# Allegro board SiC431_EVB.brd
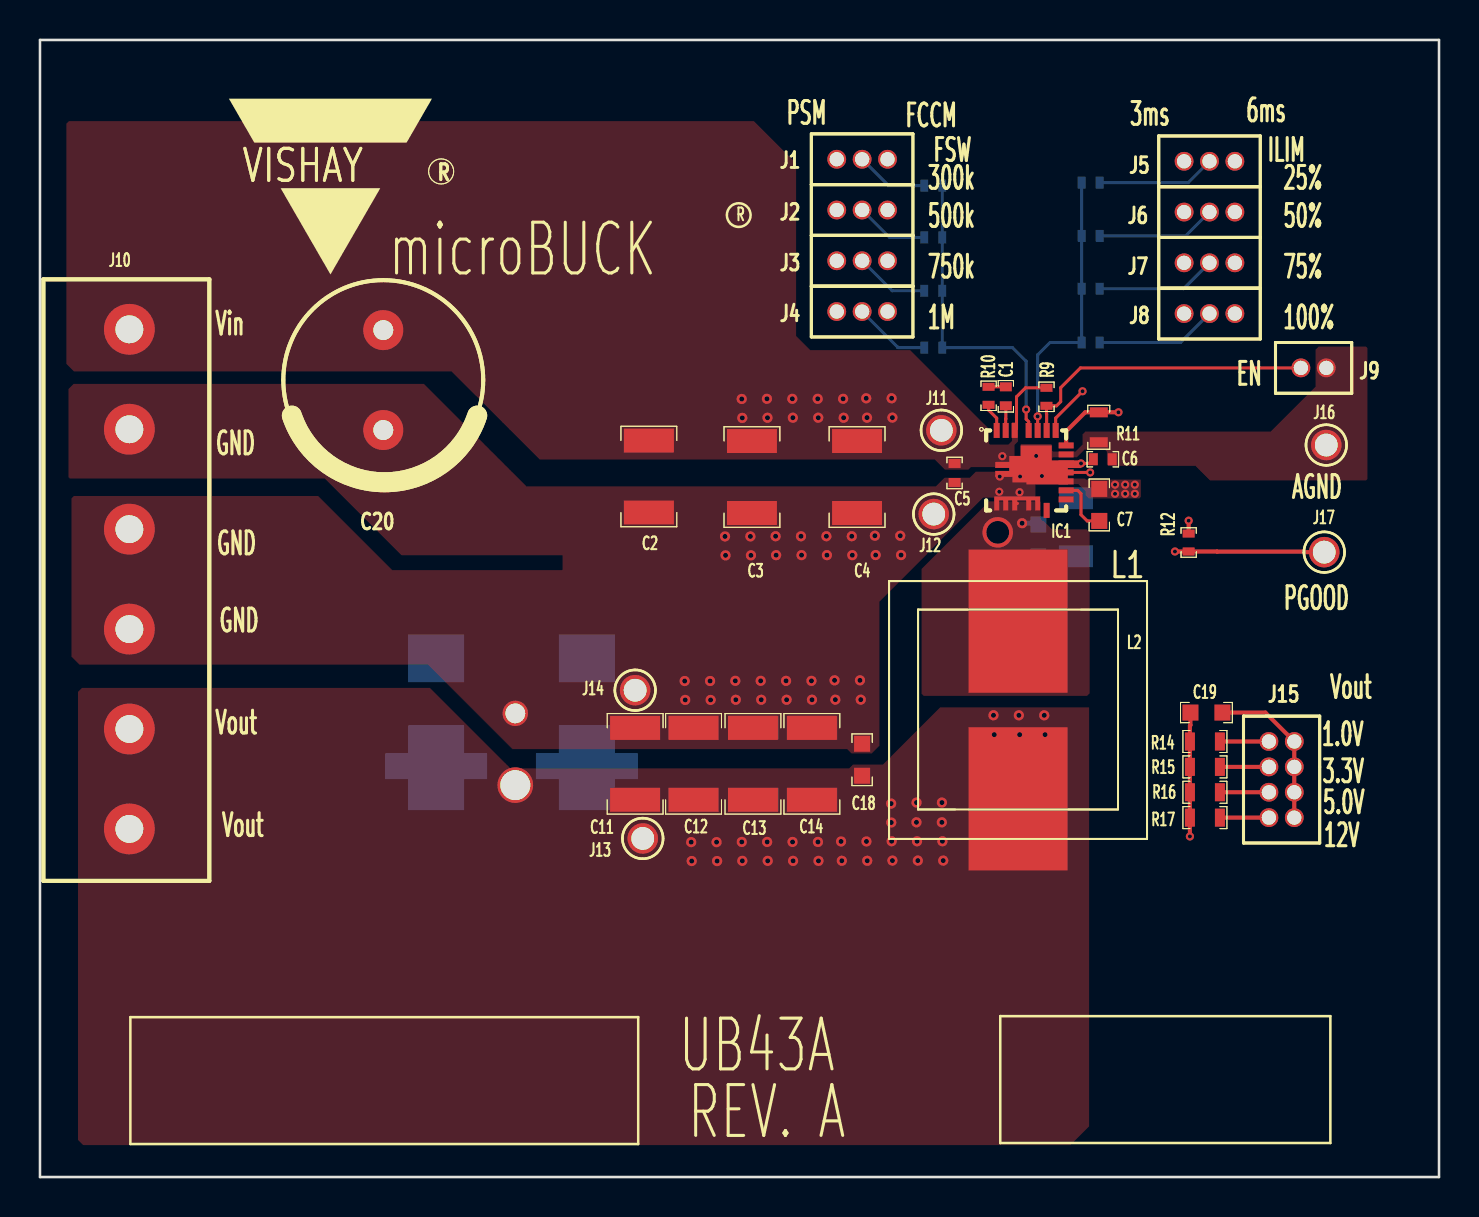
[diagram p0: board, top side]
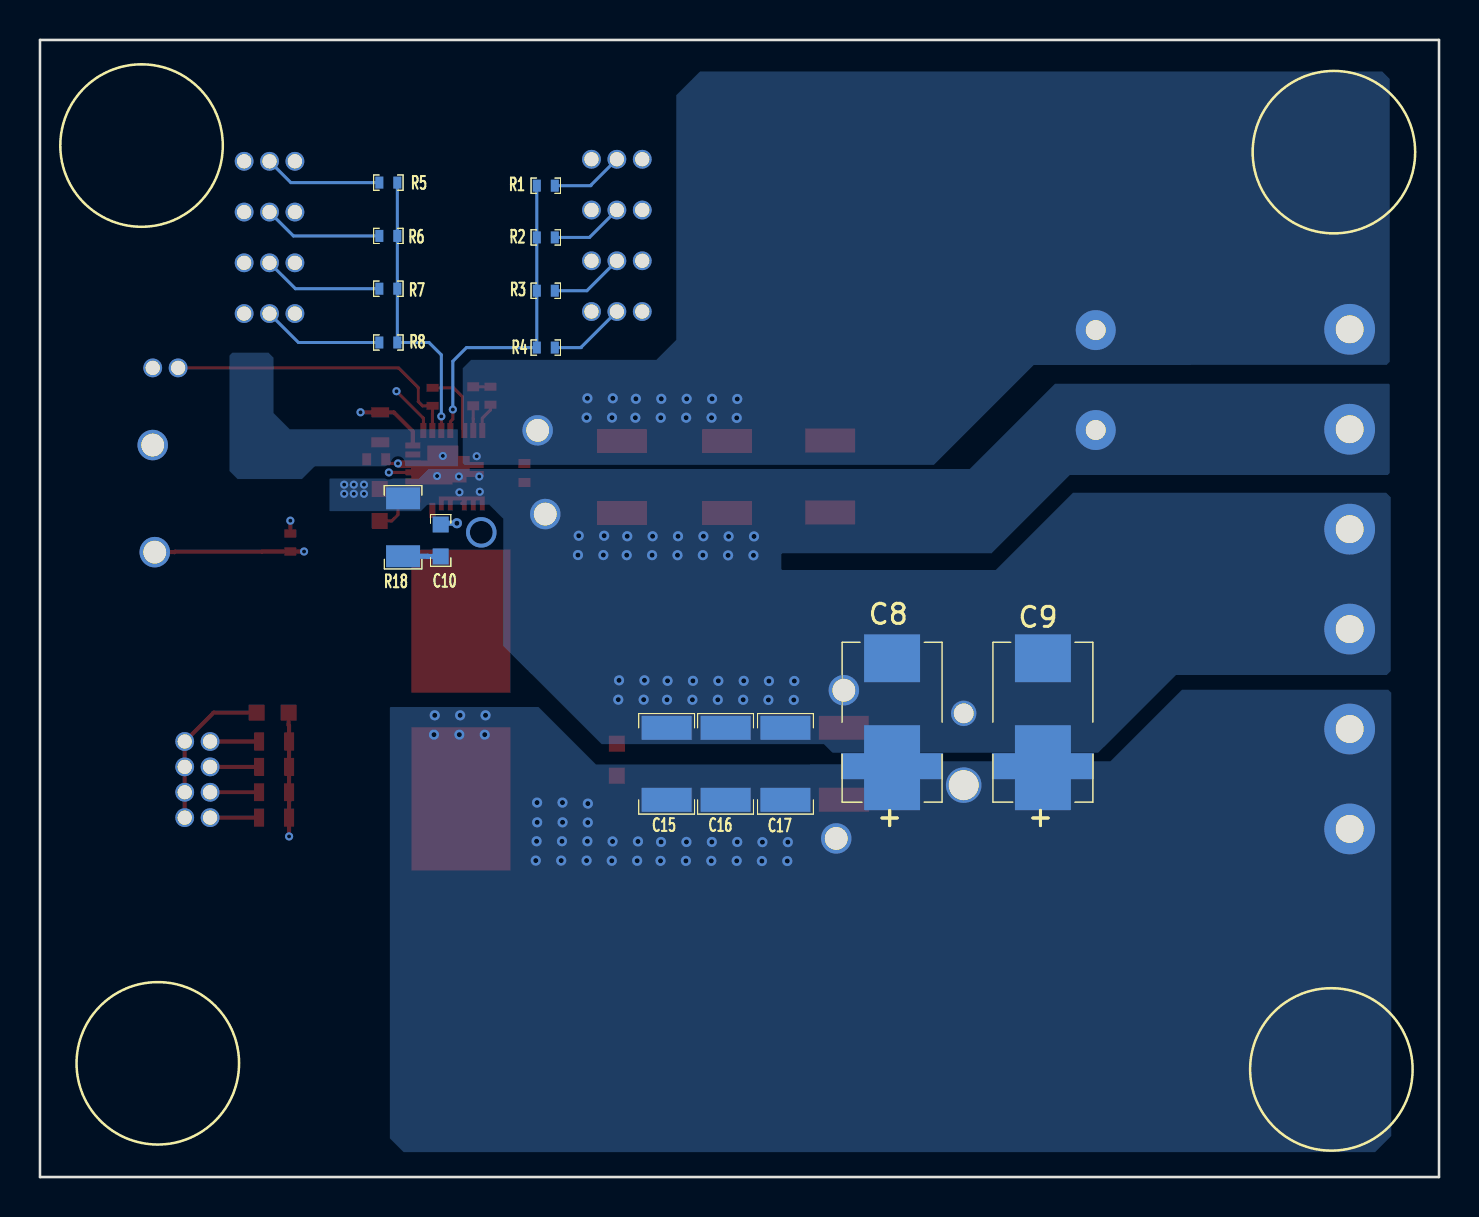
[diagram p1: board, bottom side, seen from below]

Outline 69.98 x 56.9 mm; copper layers: TOP, LAYER2, LAYER3, LAYER4, LAYER5, BOTTOM. Coordinates in mm from the lower left corner of the outline.
Outline path: 0,56.9 0,0 69.98,0 69.98,56.9 0,56.9

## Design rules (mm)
constraint set DEFAULT: min track width 0.152

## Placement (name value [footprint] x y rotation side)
C1  100n  [C0402-TDK1]  48.31 39.07 270 top
C2  22uF  [C1210-TDK]  30.45 35.05 270 top
C3  22uF  [C1210-TDK]  35.61 35.03 270 top
C4  22uF  [C1210-TDK]  40.87 35.03 270 top
C5  0.1uF  [C0402-TDK]  45.75 35.23 270 top
C6  0.1u  [C0402-TDK1]  53.16 35.92 0 top
C7  1u  [C0603-TDK1]  52.98 33.63 90 top
C8  DNP  [POSCAP]  27.36 22.76 90 bottom
C9  DNP  [POSCAP]  19.81 22.76 90 bottom
C10  DNP  [C0603-TDK1]  49.94 31.85 270 bottom
C11  22uF  [C1210-TDK]  29.77 20.68 90 top
C12  22uF  [C1210-TDK]  32.69 20.68 90 top
C13  22uF  [C1210-TDK]  35.66 20.68 90 top
C14  22uF  [C1210-TDK]  38.61 20.68 90 top
C15  22uF  [C1210-TDK]  38.63 20.68 90 bottom
C16  22uF  [C1210-TDK]  35.69 20.68 90 bottom
C17  22uF  [C1210-TDK]  32.69 20.68 90 bottom
C18  0.1u  [C0603-TDK1]  41.12 20.88 90 top
C19  22n  [C0603-TDK1]  58.34 23.24 180 top
C20  220uF  [CAP10P2X5]  17.17 39.88 270 top
IC1  SiC431  [SIC431M]  49.33 35.36 0 top
J1  CON3  [MINIJUMPER3]  42.39 50.93 180 top
J2  CON3  [MINIJUMPER3]  42.39 48.39 180 top
J3  CON3  [MINIJUMPER3]  42.39 45.85 180 top
J4  CON3  [MINIJUMPER3]  42.39 43.31 180 top
J5  CON3  [MINIJUMPER3]  59.77 50.83 180 top
J6  CON3  [MINIJUMPER3]  59.77 48.29 180 top
J7  CON3  [MINIJUMPER3]  59.77 45.75 180 top
J8  CON3  [MINIJUMPER3]  59.77 43.21 180 top
J9  CON2  [MINIJUMPER2]  64.34 40.49 180 top
J10  -  [CON6]  4.47 42.42 270 top
J11  VIN+s  [TP30]  45.09 37.36 0 top
J12  VIN-S  [TP30]  44.7 33.17 0 top
J13  VO+S  [TP30]  30.15 16.94 0 top
J14  VO-S  [TP30]  29.77 24.36 0 top
J15  CON8A  [MINIJUMPER2X4]  61.47 21.79 0 top
J16  AGND  [TP30]  64.34 36.63 0 top
J17  PGOOD  [TP30]  64.24 31.27 0 top
L1  0.22uH  [IHLP]  48.92 23.37 90 top
L2  0.22uH  [HCUVDE1]  48.92 23.39 90 top
NOREF  -  []  14.53 45.16 0 top
PB  CON2  [2PROBE]  23.77 19.61 135 top
R1  51k  [R0402-VISHAY1]  44.68 49.61 180 bottom
R2  100k  [R0402-VISHAY1]  44.68 47.02 180 bottom
R3  200k  [R0402-VISHAY1]  44.68 44.35 180 bottom
R4  510k  [R0402-VISHAY1]  44.68 41.5 180 bottom
R5  51k  [R0402-VISHAY1]  52.55 49.76 0 bottom
R6  100k  [R0402-VISHAY1]  52.55 47.09 0 bottom
R7  200k  [R0402-VISHAY1]  52.55 44.45 0 bottom
R8  510k  [R0402-VISHAY1]  52.55 41.76 0 bottom
R9  100k  [R0402-VISHAY1]  50.34 39.04 90 top
R10  0  [R0402-VISHAY1]  47.45 39.09 270 top
R11  10k  [R0603-VISHAY]  52.96 37.52 90 top
R12  100k  [R0402-VISHAY1]  57.45 31.75 90 top
R14  10k  [R0603-VISHAY]  58.27 21.79 0 top
R15  10k  [R0603-VISHAY]  58.27 20.52 0 top
R16  10k  [R0603-VISHAY]  58.27 19.25 0 top
R17  10k  [R0603-VISHAY]  58.27 17.98 0 top
R18  DNP  [R1206-VISHAY]  51.82 32.51 270 bottom

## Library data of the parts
C1-C6 C11-C19 = CAPACITOR NON-POL
C7 C10 = CAP NP
C8 C9 = POSCAP
C20 = CAP
IC1 = SiC431_2
J1-J8 = CON3: User Part Number: ***
J9 = CON2: User Part Number: ***
J10 = CON6
J11-J14 J16 J17 = CON1
J15 = CON8A
L1 L2 = INDUCTOR
PB = CON2
R1-R8 R10 R12 R14-R17 = R
R9 R11 R18 = RESISTOR

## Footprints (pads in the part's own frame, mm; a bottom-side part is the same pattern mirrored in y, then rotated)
2PROBE
  round 1.778 hole 1.499: 1(0,0)
  round 1.27 hole 0.991: 2(2.54,-2.54)
C0402-TDK
  rect 0.45x0.6 smd: 1(-0.475,0) 2(0.475,0)
C0402-TDK1
  rect 0.45x0.6 smd: 1(-0.475,0) 2(0.475,0)
C0603-TDK1
  rect 0.8x0.8 smd: 1(-0.8,0) 2(0.8,0)
C1210-TDK
  rect 1.2x2.5 smd: 1(-1.8,0) 2(1.8,0)
CAP10P2X5
  round 2 hole 1: 1(-2.5,0) 2(2.5,0)
CON6
  round 2.54 hole 1.397: 1(0,0) 2(5,0) 3(10,0) 4(15,0) 5(20,0) 6(25,0)
HCUVDE1
  custom 0.9x0.9 smd: 1(-3.65,0) 2(3.65,0)
IHLP
  rect 7.163x4.953 smd: 1(-4.445,0) 2(4.445,0)
MINIJUMPER2
  round 0.94 hole 0.711: 1(0,0) 2(1.27,0)
MINIJUMPER2X4
  round 0.94 hole 0.711: 1(0,0) 2(1.27,0) 3(0,-1.27) 4(1.27,-1.27) 5(0,-2.54) 6(1.27,-2.54) 7(0,-3.81) 8(1.27,-3.81)
MINIJUMPER3
  round 0.94 hole 0.711: 1(0,0) 2(1.27,0) 3(2.54,0)
POSCAP
  rect 2.4x2.8 smd: 1(-3.2,0) 2(3.2,0)
  custom 0.675x0.675 smd: 3(-1.5,0)
R0402-VISHAY1
  rect 0.4x0.6 smd: 1(-0.45,0) 2(0.45,0)
R0603-VISHAY
  rect 0.5x0.9 smd: 1(-0.75,0) 2(0.75,0)
R1206-VISHAY
  rect 1.1x1.7 smd: 1(-1.45,0) 2(1.45,0)
SIC431M
  custom 0.263x0.263 smd: 1(-0.65,0.2)
  round 0 smd: 2(-1.499,0.406) 4(-2.007,-0.914) 6(-0.889,-2.134) 7(-0.432,-2.184) 8(0.076,-2.184) 9(0.457,-2.159)
  custom 0.3x0.3 smd: 3(1.03,-0.1)
  custom 0.175x0.175 smd: 5(-0.45,-1.65)
  rect 0.3x0.75 smd: 10(1.025,-2) 18(1.475,2) 19(1.025,2) 20(0.575,2) 21(0.125,2) 22(-0.575,2) 23(-1.025,2) 24(-1.475,2)
  rect 0.75x0.3 smd: 11(2,-1.45) 12(2,-1) 13(2,-0.55) 14(2,-0.1) 15(2,0.35) 16(2,0.8) 17(2,1.25)
  rect 1.55x1.05 smd: 25(0.5,0.725)
TP30
  round 1.524 hole 1.143: 1(0,0)

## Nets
GND_POWER: C2.2 C3.2 C4.2 C5.2 C6.2 C7.2 C8.2 C8.3 C9.2 C9.3 C11.2 C12.2 C13.2 C14.2 C15.2 C16.2 C17.2 C18.2 C20.2 IC1.3 IC1.4 IC1.13 IC1.16 IC1.25 J1.3 J2.3 J3.3 J4.3 J5.3 J6.3 J7.3 J8.3 J9.1 J10.2 J10.3 J10.4 J12.1 J14.1 J16.1 PB.2 R11.1 R18.1
VDD1: C6.1 IC1.15 J1.1 J2.1 J3.1 J4.1 J5.1 J6.1 J7.1 J8.1 R12.2
VIN: C2.1 C3.1 C4.1 C5.1 C20.1 IC1.1 IC1.2 IC1.22 J10.1 J11.1 R9.2
BOOT: C1.2 IC1.23
MODE1: IC1.21 R1.1 R2.1 R3.1 R4.1
MODE2: IC1.20 R5.1 R6.1 R7.1 R8.1
PGD: IC1.14 J17.1 R12.1
PHASE: IC1.24 R10.2
VO: C8.1(P) C9.1(P) C11.1 C12.1 C13.1 C14.1 C15.1 C16.1 C17.1 C18.1 C19.2 IC1.18(VOUT) J10.5 J10.6 J13.1 L1.1 L2.1 PB.1 R14.1 R15.1 R16.1 R17.1
N10425435: C10.1 IC1.5 IC1.6 IC1.7 IC1.8 IC1.9 L1.2 L2.2
N10425735: IC1.19 J9.2 R9.1
N10425943: C1.1 R10.1
N10491860: C19.1 IC1.17 J15.2 J15.4 J15.6 J15.8 R11.2
N10497600: C7.1 IC1.12
N10592056: J1.2 R1.2
N10592279: J2.2 R2.2
N10592308: J3.2 R3.2
N10592330: J4.2 R4.2
N10602058: J5.2 R5.2
N10602062: J6.2 R6.2
N10602066: J7.2 R7.2
N10602070: J8.2 R8.2
N10625993: C10.2 R18.2
N10654889: J15.1 R14.2
N10668036: J15.3 R15.2
N10668228: J15.5 R16.2
N10668284: J15.7 R17.2

Pads without a net: IC1 10 11

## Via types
v1: diameter 0.508, hole 0.254, TOP to BOTTOM, 81 vias
v2: diameter 1.524, hole 1.143, TOP to BOTTOM, 1 via
v3: diameter 0.406, hole 0.203, TOP to BOTTOM, 22 vias

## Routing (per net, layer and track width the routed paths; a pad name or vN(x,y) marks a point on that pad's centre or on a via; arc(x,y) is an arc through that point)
GND_POWER:
  vias: v1(32.25,24.82) v1(32.27,23.87) v1(33.52,24.82) v1(33.54,23.87) v1(34.26,32.05) v1(34.29,31.11) v1(34.78,24.83) v1(34.8,23.88) v1(35.53,32.05) v1(35.56,31.11) v1(36.05,24.83) v1(36.07,23.88) v1(36.79,32.06) v1(36.82,31.12) v1(37.32,24.83) v1(37.34,23.88) v1(38.06,32.06) v1(38.09,31.12) v1(38.59,24.83) v1(38.61,23.88) v1(39.33,32.06) v1(39.36,31.12) v1(39.74,24.85) v1(39.78,23.89) v1(40.6,32.06) v1(40.63,31.12) v1(41.01,24.85) v1(41.05,23.89) v1(41.76,32.09) v1(41.8,31.12) v1(43.03,32.09) v1(43.07,31.12) v3(48.01,35.05) v3(47.98,34.29) v3(49.02,35.05) v3(49,34.26) v3(49.83,36.08) v3(50.11,35.08) v3(53.77,34.65) v3(53.77,34.19) v3(54.28,34.65) v3(54.28,34.19) v3(54.76,34.65) v3(54.76,34.19)
VDD1: length 51.1
  TOP w0.152: 52.48,35.71 52.48,35.71 C6.1 ; 52.48,35.71 52.68,35.91 52.68,35.92 ; 52.48,35.71 v3(52.07,35.71) IC1.15
  TOP w0.203: R12.2 v3(57.45,32.84)
  LAYER3 w0.152: 51.56,38.88 48.95,41.5 43.15,41.5 42.39,42.27 J4.1 J3.1 J2.1 J1.1 ; 51.56,38.88 51.56,40.01 52.6,41.05 59.03,41.05 59.77,41.78 J8.1 J7.1 J6.1 J5.1 ; 51.56,38.88 52.07,38.38 v3(52.07,35.71) 55.25,35.71 57.45,33.5 v3(57.45,32.84)
VIN: length 3.4
  TOP w0.152: R9.2 49.29,39.49 48.84,39.04 48.84,37.45 IC1.22
  vias: v1(35.1,38.93) v1(35.13,37.99) v1(36.36,38.94) v1(36.39,37.99) v1(37.63,38.94) v1(37.66,37.99) v1(38.9,38.94) v1(38.93,37.99) v1(40.17,38.94) v1(40.2,37.99) v1(41.33,38.97) v1(41.37,38) v1(42.6,38.97) v1(42.64,38) v3(48.13,36.07)
BOOT: length 1.2
  TOP w0.152: IC1.23 48.3,37.94 48.31,37.94 C1.2
MODE1: length 16.1
  TOP w0.152: IC1.21 49.45,37.8 49.33,37.92 v3(49.33,38.4)
  BOTTOM w0.152: R1.1 R2.1 R3.1 R4.1 48.64,41.5 49.33,40.82 v3(49.33,38.4)
MODE2: length 14.2
  TOP w0.152: IC1.20 v3(49.9,38.06)
  BOTTOM w0.152: v3(49.9,38.06) 49.9,41.14 50.52,41.76 R8.1 R7.1 R6.1 R5.1
PGD: length 16
  TOP w0.152: v3(52.53,35.26) IC1.14
  TOP w0.203: v3(56.77,31.3) R12.1 58.87,31.3 58.88,31.29 63.22,31.29 63.25,31.27 J17.1
  LAYER3 w0.152: v3(56.77,31.3) 56.77,33.68 55.19,35.26 v3(52.53,35.26)
PHASE: length 1.5
  TOP w0.152: IC1.24 47.85,37.97 47.45,38.38 R10.2
VO: length 63.2
  TOP w0.152: IC1.18 50.8,37.97 v3(52.15,39.32)
  TOP w0.203: v3(57.52,17.04) R17.1 R16.1 R15.1 R14.1 57.52,22.59 57.54,22.61 C19.2
  LAYER3 w0.152: J13.1 31.9,15.19 56.77,15.19 57.52,15.94 v3(57.52,17.04) 58.12,17.64 58.12,33.35 v3(52.15,39.32)
  vias: v1(32.57,16.76) v1(32.6,15.81) v1(33.84,16.76) v1(33.87,15.81) v1(35.1,16.77) v1(35.13,15.82) v1(36.37,16.77) v1(36.4,15.82) v1(37.64,16.77) v1(37.67,15.82) v1(38.91,16.77) v1(38.94,15.82) v1(40.07,16.79) v1(40.11,15.83) v1(41.34,16.79) v1(41.38,15.83) v1(42.57,18.69) v1(42.58,17.74) v1(42.6,16.8) v1(42.64,15.83) v1(43.84,18.74) v1(43.84,17.75) v1(43.87,16.8) v1(43.91,15.83) v1(45.11,18.74) v1(45.11,17.75) v1(45.14,16.8) v1(45.18,15.83) v1(47.69,23.1) v1(47.73,22.14) v1(48.96,23.1) v1(49,22.14) v1(50.23,23.1) v1(50.27,22.14)
N10425435: length 0.8
  BOTTOM w0.254: v1(49.12,32.72) 49.87,32.72 C10.1
  vias: v2(47.9,32.26)
N10425735: length 15.2
  TOP w0.152: J9.2 52.04,40.49 51.05,39.5 51.05,38.8 50.85,38.59 R9.1 50.34,38.19 50.35,38.18 IC1.19
N10425943: length 0.9
  TOP w0.152: C1.1 R10.1
N10491860: length 31.8
  TOP w0.203: C19.1 61.29,23.24 J15.2 J15.4 J15.6 J15.8 ; v3(53.94,38.27) R11.2 52.28,38.27 51.33,37.31 IC1.17
  LAYER3 w0.152: v3(53.94,38.27) 62.74,29.47 J15.2
N10497600: length 2.9
  TOP w0.152: C7.1 52.38,32.83 52.07,33.14 52.07,34.19 51.91,34.36 IC1.12
N10592056: length 3.7
  BOTTOM w0.152: R1.2 42.42,49.61 42.42,49.63 J1.2
N10592279: length 3.7
  BOTTOM w0.152: R2.2 42.49,47.02 J2.2
N10592308: length 3.7
  BOTTOM w0.152: J3.2 42.62,44.35 R3.2
N10592330: length 3.9
  BOTTOM w0.152: J4.2 42.91,41.52 42.91,41.5 R4.2
N10602058: length 5.9
  BOTTOM w0.152: J5.2 57.43,49.76 R5.2
N10602062: length 6
  BOTTOM w0.152: R6.2 57.3,47.09 J6.2
N10602066: length 6
  BOTTOM w0.152: R7.2 57.2,44.45 J7.2
N10602070: length 6.1
  BOTTOM w0.152: J8.2 57.05,41.76 R8.2
N10625993: length 1.9
  BOTTOM w0.254: R18.2 50.6,31.06 50.59,31.05 C10.2
N10654889: length 2.5
  TOP w0.203: J15.1 R14.2
N10668036: length 2.5
  TOP w0.203: J15.3 R15.2
N10668228: length 2.5
  TOP w0.203: J15.5 R16.2
N10668284: length 2.5
  TOP w0.203: J15.7 R17.2

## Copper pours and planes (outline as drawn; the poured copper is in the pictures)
GND_POWER on TOP: 19.2,39.69 24.34,34.56 44.81,34.56 45.24,34.99 46.51,34.99 46.81,35.29 48.95,35.29 49.05,35.39 49.05,36.65 49.07,36.68 50.57,36.68 50.62,36.63 50.62,36.35 50.67,36.3 51.79,36.3 52.15,36.65 52.15,37.16 52.29,37.3 61.56,37.3 63.8,39.55 63.8,41.4 63.96,41.55 66.32,41.55 66.4,41.48 66.4,34.93 66.33,34.86 58.52,34.86 57.8,35.59 53.44,35.59 53.37,35.66 53.37,36.3 53.26,36.4 52.25,36.4 51.87,36.02 50.67,36.02 50.62,35.97 50.62,35.03 50.7,34.95 52.27,34.95 52.32,34.9 55.04,34.9 55.07,34.87 55.07,34.04 54.99,33.96 52.45,33.96 52.3,34.11 52.3,34.32 51.94,34.67 50.62,34.67 50.6,34.7 49.83,34.7 49.79,34.65 49.79,34.07 49.71,34 47.17,34 44.38,31.2 44.38,31.18 41.99,28.79 41.99,21.58 41.61,21.2 40.59,21.2 40.37,21.41 23.63,21.41 19.41,25.64 1.97,25.64 1.57,26.04 1.57,33.96 1.69,34.07 13.92,34.07 17.63,30.37 26.11,30.37 26.14,30.39 26.14,31.09 26.11,31.12 18.08,31.12 14.25,34.95 1.5,34.95 1.42,35.03 1.42,39.42 1.69,39.69
GND_POWER on BOTTOM: 19.2,39.69 23.47,35.43 50.55,35.43 51.02,34.95 55.47,34.95 55.5,34.93 55.5,33.35 55.47,33.32 50.93,33.32 50.61,33.64 47.5,33.64 46.8,32.94 46.8,26.58 41.89,21.66 30.76,21.66 30.36,21.25 30.36,21.23 17.04,21.23 13.16,25.12 2.62,25.12 2.41,25.32 2.41,34.01 2.64,34.24 18.31,34.24 22.18,30.37 32.84,30.37 32.9,30.42 32.9,31.16 32.84,31.21 22.38,31.21 18.46,35.13 2.57,35.13 2.46,35.23 2.46,39.65 2.51,39.69
GND_POWER on BOTTOM: 49.07,35.59 49.07,37.39 49.1,37.41 57.48,37.41 58.29,38.23 58.29,41 58.55,41.25 60.35,41.25 60.5,41.1 60.5,35.33 60.1,34.93 56.87,34.93 56.24,35.56 49.1,35.56
GND_POWER on LAYER2: 37.37,52.17 40.09,52.17 40.44,51.82 40.44,42.7 41.1,42.04 47.73,42.04 48.55,42.85 48.55,52.2 57.73,52.2 57.81,52.12 57.81,36.02 57.63,35.84 55.63,35.84 55.6,35.81 49.38,35.81 44.78,40.41 37.5,40.41 36.86,41.05 36.86,51.66
GND_POWER on LAYER2: 39.94,39.7 44.33,35.31 52.83,35.31 56.77,35.31 57.05,35.03 57.05,31.1 60.68,27.46 60.68,15.77 60.68,15.77 60.68,1.8 59.97,1.09 1.78,1.09 1.52,1.35 1.52,33.91 1.7,34.09 18.5,34.09 22.2,30.38 32.85,30.38 32.9,30.43 32.9,31.17 32.85,31.22 22.41,31.22 18.39,35.24 1.49,35.24 1.35,35.38 1.35,39.65 1.4,39.7
GND_POWER on LAYER3: 39.9,39.7 44.3,35.31 51.38,35.31 51.79,34.9 55.09,34.9 56.16,33.83 56.16,2.51 55.3,1.65 2.82,1.65 1.88,2.59 1.88,33.99 1.98,34.09 18.47,34.09 22.17,30.38 32.84,30.38 32.89,30.43 32.89,31.17 32.84,31.22 22.38,31.22 18.36,35.23 1.75,35.23 1.6,35.38 1.6,39.42 1.88,39.7
GND_POWER on LAYER4: 39.93,39.69 44.32,35.3 55.96,35.3 56.39,34.87 56.39,31.74 60.35,27.78 60.35,1.29 59.72,0.66 3.12,0.66 1.52,2.26 1.52,33.91 1.7,34.08 18.49,34.08 22.19,30.38 32.84,30.38 32.89,30.43 32.89,31.17 32.85,31.21 22.4,31.21 18.38,35.23 1.42,35.23 1.3,35.36 1.3,39.6 1.39,39.69
GND_POWER on LAYER4: 26.49,51.94 31.63,51.94 31.83,51.74 31.83,42.18 32.21,41.8 36.86,41.8 37.67,42.62 37.67,51.96 50.93,51.96 51.16,51.74 51.16,36.11 50.65,35.6 44.73,35.6 40.16,40.18 26.62,40.18 25.99,40.81 25.99,51.43
GND_POWER on LAYER5: 19.2,39.7 23.47,35.43 55.45,35.43 55.5,35.38 55.5,33.3 55.45,33.25 46.94,33.25 46.63,32.94 46.63,26.24 41.81,21.41 24.64,21.41 20.88,25.17 3.15,25.17 2.62,25.7 2.62,33.91 2.79,34.09 18.47,34.09 22.17,30.38 32.84,30.38 32.89,30.43 32.89,31.17 32.84,31.22 22.38,31.22 18.31,35.28 2.82,35.28 2.51,35.59 2.51,39.5 2.72,39.7
VIN on TOP: 37.82,42.09 38.53,41.38 43.53,41.38 47.47,37.43 47.47,36.69 47.51,36.65 48.44,36.65 48.62,36.83 48.62,37.74 48.64,37.77 48.89,37.77 48.92,37.74 48.92,36.8 48.84,36.73 48.74,36.63 48.74,35.55 48.72,35.52 46.56,35.52 46.43,35.39 45.26,35.39 44.76,35.9 25,35.9 20.59,40.31 1.7,40.31 1.32,40.69 1.32,52.7 1.45,52.83 35.71,52.83 37.82,50.72
VIN on BOTTOM: 39.15,40.89 48.42,40.89 48.83,40.47 48.83,35.74 48.73,35.63 25.27,35.63 20.27,40.63 12.37,40.63 12.37,40.64 2.62,40.64 2.46,40.79 2.46,54.94 2.84,55.32 36.96,55.32 38.15,54.13 38.15,41.88
VIN on LAYER5: 38.99,41.39 43.52,41.39 48.4,41.39 48.92,40.87 48.92,37.77 48.95,37.74 48.95,35.59 48.92,35.56 25.35,35.56 20.27,40.64 2.77,40.64 2.31,41.1 2.31,55.5 2.74,55.93 36.17,55.93 38.15,53.95 38.15,42.24 38.99,41.4
VO on TOP: 45.04,23.51 42.17,20.64 40.67,20.64 40.48,20.45 26.85,20.45 26.85,20.45 23.53,20.45 19.51,24.47 2.09,24.47 1.91,24.28 1.91,1.85 2.16,1.6 51.54,1.6 52.48,2.54 52.48,23.48 52.45,23.51
VO on BOTTOM: 45.04,23.51 42.17,20.64 31.5,20.64 31.49,20.65 29.46,20.65 29.31,20.8 16.43,20.8 12.85,24.38 2.54,24.38 2.39,24.23 2.39,2.06 3.2,1.24 51.79,1.24 52.48,1.93 52.48,23.5 52.46,23.51
VO on LAYER5: 45.03,23.52 42.23,20.71 26.4,20.71 26.39,20.73 24.03,20.73 20.27,24.49 3.15,24.49 2.87,24.21 2.87,2.26 3.81,1.32 51.44,1.32 52.48,2.36 52.48,23.5 52.45,23.52
N10425435 on TOP: 47.47,33.81 50.01,33.81 50.06,33.76 50.06,32.97 50.62,32.41 52.35,32.41 52.5,32.26 52.5,24.21 52.37,24.08 44.2,24.08 44.09,24.18 44.09,30.43

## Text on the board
Ref Des/Silkscreen Top: R | Vin | Vout | GND | PSM | FCCM | 300k | 500k | 750k | 1M | FSW | 3ms | EN | 6ms | ILIM | 25% | 50% | 75% | 100% | PGOOD | AGND | 1.0V | 3.3V | 5.0V | 12V | microBUCK | UB43A | REV. A
FAB: Layer4 | Layer3 | Layer2 | Layer5 | Bottom | Top | TOTAL THICKNESS - 0.62 -.008/+.005 | 2OZ | 1 THIS IS A 6 LAYER BOARD WITH COMPONENTS ON BOTH SIDES. | 3 SILKSCREEN BOTH SIDES WITH WHITE NON CONDUCTIVE EPOXY BASED INK | 4 IMMERSION GOLD FINISH | 2 SMT LAND PATTERNS THAT HAVE A FINISHED PAD WIDTH RANGING FROM | 6 Material Type: IT175A | 5 GREEN SOLDER MASK | .012 TO .015 MUST USE THE FOLLOWING TOLERANCE, +.002-.0005. | PB VENDOR TO ADJUST ARTWORK TO COMPENSATE FOR ETCH PROCESS. | NOTES: UNLESS OTHERWISE SPECIFIED:
